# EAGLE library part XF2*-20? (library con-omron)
OMRON FPC Connector Source : http://www.omron.com/ecb/products/pdf/fpc.pdf
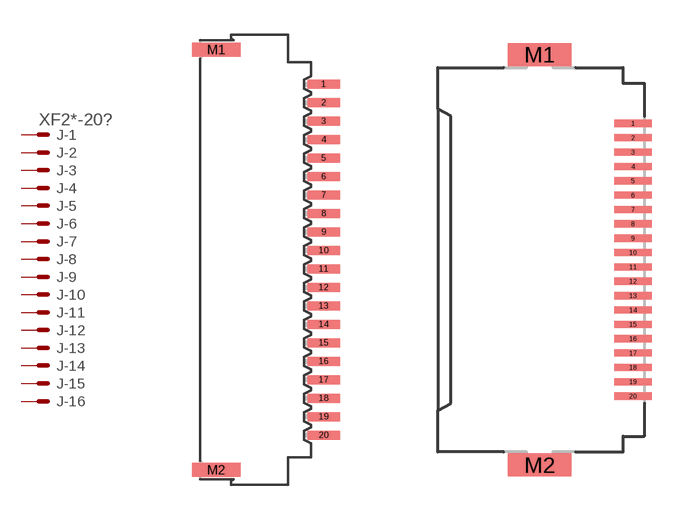
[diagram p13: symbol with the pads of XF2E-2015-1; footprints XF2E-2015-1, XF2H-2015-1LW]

Designator prefix J; gates -1=PV -2=P -3=P -4=P -5=P -6=P -7=P -8=P -9=P -10=P -11=P -12=P -13=P -14=P -15=P -16=P -17=P -18=P -19=P -20=P

## XF2E-2015-1 (MPN: XF2E-2015-1; OC_FARNELL: unknown; OC_NEWARK: 37M9453)  [XF2E-2015-1]
1  -1:MSV  pas
2  -2:MS  pas
3  -3:MS  pas
4  -4:MS  pas
5  -5:MS  pas
6  -6:MS  pas
7  -7:MS  pas
8  -8:MS  pas
9  -9:MS  pas
10  -10:MS  pas
11  -11:MS  pas
12  -12:MS  pas
13  -13:MS  pas
14  -14:MS  pas
15  -15:MS  pas
16  -16:MS  pas
17  -17:MS  pas
18  -18:MS  pas
19  -19:MS  pas
20  -20:MS  pas

## XF2H-2015-1LW (OC_FARNELL: unknown; OC_NEWARK: unknown)  [XF2H-2015-1LW]
Pads as for XF2E-2015-1

## XF2J-2024-11 (MF: OMRON COMPONENTS USA; MPN: XF2J-2024-11; OC_FARNELL: 1430937; OC_NEWARK: 29C7825)  [XF2J-2024-11]
Pads as for XF2E-2015-1

## XF2J-2024-12 (MPN: XF2J-2024-12A; OC_FARNELL: 1430941; OC_NEWARK: 59M3514)  [XF2J-2024-12]
Pads as for XF2E-2015-1

## XF2L-2035-1 (MPN: XF2L-2035-1; OC_FARNELL: unknown; OC_NEWARK: 37M0893)  [XF2L-2035-1]
Pads as for XF2E-2015-1

## Footprint XF2E-2015-1 (pad centres in mm)
Non-ZIF Type (0.8 mm-pitch) Source : http://www.omron.com/ecb/products/pdf/fpc.pdf
smd 1.4 x 0.4: 1 2.54,7.6; 2 2.54,6.8; 3 2.54,6; 4 2.54,5.2; 5 2.54,4.4; 6 2.54,3.6; 7 2.54,2.8; 8 2.54,2; 9 2.54,1.2; 10 2.54,0.4; 11 2.54,-0.4; 12 2.54,-1.2; 13 2.54,-2; 14 2.54,-2.8; 15 2.54,-3.6; 16 2.54,-4.4; 17 2.54,-5.2; 18 2.54,-6; 19 2.54,-6.8; 20 2.54,-7.6
smd 2.1 x 0.6: M1 -2.11,9.1; M2 -2.11,-9.1

## Footprint XF2H-2015-1LW (pad centres in mm)
Standard Rotary Backlock Type (0.5 mm-pitch) Source : http://www.omron.com/ecb/products/pdf/fpc.pdf
smd 1.3 x 0.25: 1 3.175,4.75; 2 3.175,4.25; 3 3.175,3.75; 4 3.175,3.25; 5 3.175,2.75; 6 3.175,2.25; 7 3.175,1.75; 8 3.175,1.25; 9 3.175,0.75; 10 3.175,0.25; 11 3.175,-0.25; 12 3.175,-0.75; 13 3.175,-1.25; 14 3.175,-1.75; 15 3.175,-2.25; 16 3.175,-2.75; 17 3.175,-3.25; 18 3.175,-3.75; 19 3.175,-4.25; 20 3.175,-4.75
smd 2.2 x 0.8: M1 -0.075,7.15; M2 -0.075,-7.15

## Footprint XF2J-2024-11 (pad centres in mm)
ZIF Slide-locking Type (0.5 mm-pitch) Standard Source : http://www.omron.com/ecb/products/pdf/fpc.pdf
smd 1.6 x 0.5: 1 1.2,4.75; 2 -1.2,4.25; 3 1.2,3.75; 4 -1.2,3.25; 5 1.2,2.75; 6 -1.2,2.25; 7 1.2,1.75; 8 -1.2,1.25; 9 1.2,0.75; 10 -1.2,0.25; 11 1.2,-0.25; 12 -1.2,-0.75; 13 1.2,-1.25; 14 -1.2,-1.75; 15 1.2,-2.25; 16 -1.2,-2.75; 17 1.2,-3.25; 18 -1.2,-3.75; 19 1.2,-4.25; 20 -1.2,-4.75
smd 2.9 x 1.4: M1 0,6.45; M2 0,-6.45

## Footprint XF2J-2024-12 (pad centres in mm)
ZIF Slide-locking Type (0.5 mm-pitch) Reverse Source : http://www.omron.com/ecb/products/pdf/fpc.pdf
smd 1.6 x 0.5: 1 -1.2,4.75; 2 1.2,4.25; 3 -1.2,3.75; 4 1.2,3.25; 5 -1.2,2.75; 6 1.2,2.25; 7 -1.2,1.75; 8 1.2,1.25; 9 -1.2,0.75; 10 1.2,0.25; 11 -1.2,-0.25; 12 1.2,-0.75; 13 -1.2,-1.25; 14 1.2,-1.75; 15 -1.2,-2.25; 16 1.2,-2.75; 17 -1.2,-3.25; 18 1.2,-3.75; 19 -1.2,-4.25; 20 1.2,-4.75
smd 2.9 x 1.4: M1 0,6.45; M2 0,-6.45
